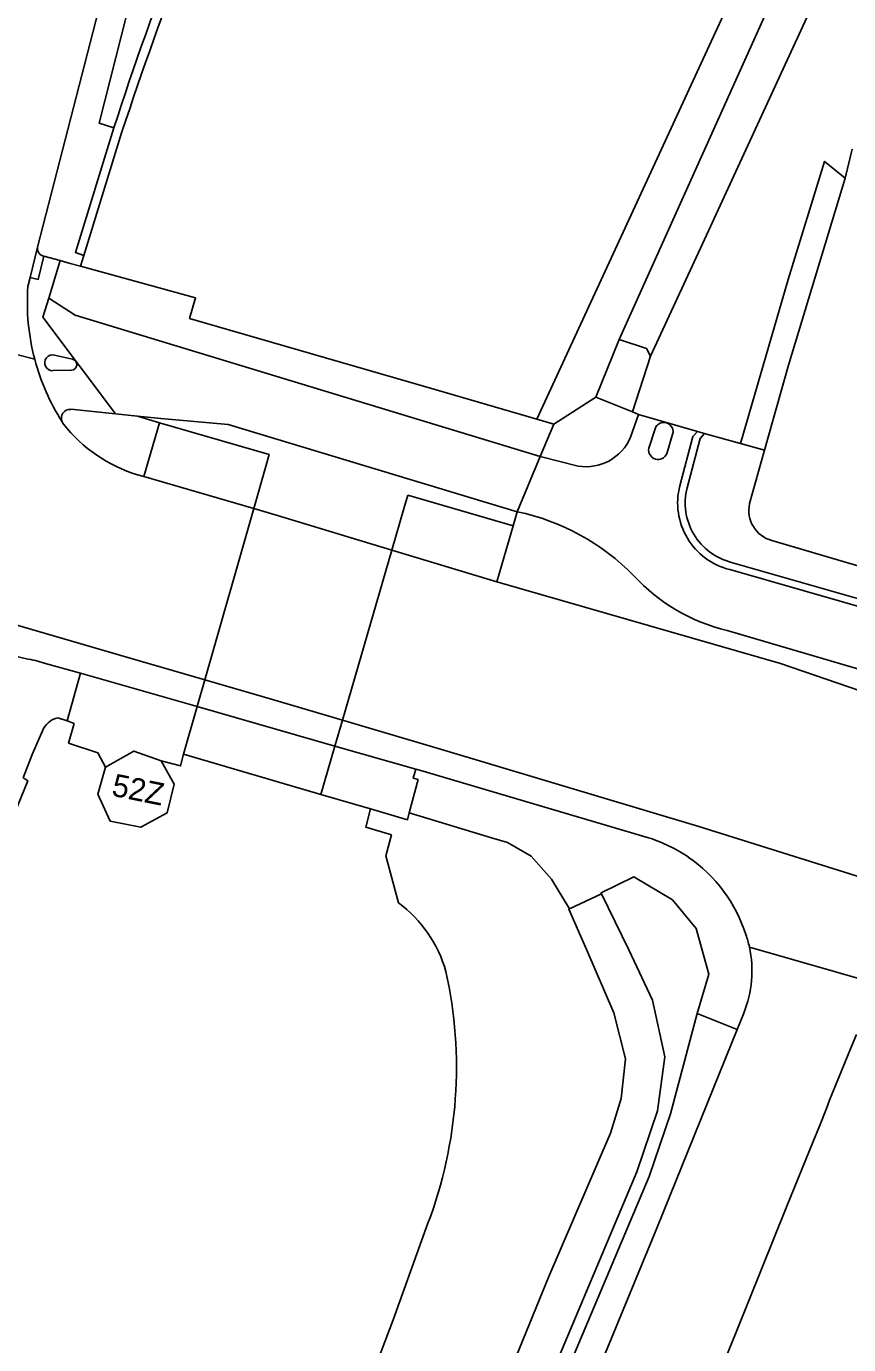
# Model space of a CAD drawing. Extents: x 194485 to 197793, y 468269 to 470822.
# Drawn here: x 194827.4 to 194871.3, y 469975.4 to 470045.7 of the extents above; entities that cross this region are included whole.
import ezdxf

# ---------------------------------------------------------------- set-up
doc = ezdxf.new("R2010")
doc.units = 0
for name, color, linetype in [('BGT grensvlak onbegroeid terreindeel', 7, 'Continuous'), ('BGT grensvlak overbruggingsdeel plus 1', 7, 'Continuous'), ('BGT grensvlak pand op maaiveld', 7, 'Continuous'), ('BGT grensvlak scheiding', 7, 'Continuous'), ('BGT grensvlak vegetatieobject', 7, 'Continuous'), ('BGT grensvlak waterdeel', 7, 'Continuous'), ('BGT grensvlak wegdeel', 7, 'Continuous'), ('BGT grensvlak wegdeel plus 1', 7, 'Continuous'), ('BGT lijnelement scheiding kademuur', 7, 'Continuous'), ('BGT tekst huisnummerreeks', 7, 'Continuous'), ('GEM grensvlak beperking object', 7, 'Continuous')]:
    doc.layers.add(name, color=color, linetype=linetype)

msp = doc.modelspace()

# ---------------------------------------------------------------- linework, layer by layer
at = {"layer": 'BGT grensvlak onbegroeid terreindeel'}
msp.add_line((194840.206, 470022.301), (194839.549, 470019.999), dxfattribs=at)
msp.add_line((194840.206, 470022.301), (194839.549, 470019.999), dxfattribs=at)
msp.add_lwpolyline([(194834.524, 470024.573), (194840.367, 470022.867), (194840.206, 470022.301)], dxfattribs=at)
msp.add_lwpolyline([(194834.524, 470024.573), (194840.367, 470022.867), (194840.206, 470022.301)], dxfattribs=at)
at = {"layer": 'BGT grensvlak overbruggingsdeel plus 1'}
for p, q in [((194828.616, 470031.214), (194829.221, 470033.217)), ((194828.616, 470031.214), (194829.221, 470033.217)), ((194833.352, 470024.915), (194832.171, 470025.038)), ((194833.352, 470024.915), (194832.171, 470025.038)), ((194833.352, 470024.915), (194832.171, 470025.038)), ((194833.352, 470024.915), (194834.524, 470024.573)), ((194833.352, 470024.915), (194834.524, 470024.573)), ((194834.524, 470024.573), (194833.691, 470021.696)), ((194855.556, 470024.502), (194854.65, 470024.764)), ((194855.556, 470024.502), (194854.65, 470024.764)), ((194855.556, 470024.502), (194854.65, 470024.764)), ((194855.556, 470024.502), (194854.833, 470022.772)), ((194855.556, 470024.502), (194854.833, 470022.772)), ((194855.556, 470024.502), (194854.833, 470022.772)), ((194854.833, 470022.772), (194853.6, 470019.823)), ((194854.833, 470022.772), (194853.6, 470019.823)), ((194854.833, 470022.772), (194853.6, 470019.823)), ((194833.691, 470021.696), (194839.549, 470019.999)), ((194836.943, 470010.858), (194839.549, 470019.999)), ((194836.943, 470010.858), (194839.549, 470019.999)), ((194839.549, 470019.999), (194840.821, 470019.631)), ((194839.549, 470019.999), (194840.821, 470019.631)), ((194840.821, 470019.631), (194846.917, 470017.781)), ((194840.821, 470019.631), (194846.917, 470017.781)), ((194853.6, 470019.823), (194853.382, 470019.067)), ((194853.6, 470019.823), (194853.382, 470019.067)), ((194853.6, 470019.823), (194853.382, 470019.067)), ((194853.382, 470019.067), (194852.523, 470016.08)), ((194853.382, 470019.067), (194852.523, 470016.08)), ((194853.382, 470019.067), (194852.523, 470016.08)), ((194844.284, 470008.708), (194846.917, 470017.781)), ((194844.284, 470008.708), (194846.917, 470017.781)), ((194846.917, 470017.781), (194852.523, 470016.08)), ((194846.917, 470017.781), (194852.523, 470016.08)), ((194836.538, 470009.439), (194836.943, 470010.858)), ((194835.81, 470006.886), (194836.538, 470009.439)), ((194843.879, 470007.314), (194844.284, 470008.708)), ((194843.879, 470007.314), (194844.284, 470008.708)), ((194843.136, 470004.745), (194835.81, 470006.886)), ((194843.879, 470007.314), (194843.136, 470004.745)), ((194843.879, 470007.314), (194843.136, 470004.745))]:
    msp.add_line(p, q, dxfattribs=at)
for points in [[(194829.221, 470033.217), (194829.753, 470033.07), (194830.318, 470032.914)], [(194829.221, 470033.217), (194829.753, 470033.07), (194830.318, 470032.914)], [(194854.65, 470024.764), (194849.288, 470026.317), (194836.133, 470030.126), (194836.444, 470031.223), (194830.318, 470032.914)], [(194854.65, 470024.764), (194849.288, 470026.317), (194836.133, 470030.126), (194836.444, 470031.223), (194830.318, 470032.914)], [(194854.65, 470024.764), (194849.288, 470026.317), (194836.133, 470030.126), (194836.444, 470031.223), (194830.318, 470032.914)], [(194832.171, 470025.038), (194828.309, 470030.198), (194828.616, 470031.214)], [(194832.171, 470025.038), (194828.309, 470030.198), (194828.616, 470031.214)], [(194832.171, 470025.038), (194828.309, 470030.198), (194828.616, 470031.214)]]:
    msp.add_lwpolyline(points, dxfattribs=at)
at = {"layer": 'BGT grensvlak pand op maaiveld'}
for points in [[(194831.651, 470006.204), (194833.161, 470007.055), (194834.611, 470006.546)], [(194831.651, 470006.204), (194831.231, 470004.754), (194831.892, 470003.324), (194833.522, 470002.995), (194834.931, 470003.765), (194835.311, 470005.286), (194834.611, 470006.546)]]:
    msp.add_lwpolyline(points, dxfattribs=at)
at = {"layer": 'BGT grensvlak scheiding'}
msp.add_line((194832.525, 470040.079), (194830.496, 470033.492), dxfattribs=at)
msp.add_line((194832.525, 470040.079), (194830.496, 470033.492), dxfattribs=at)
for points in [[(194832.096, 470040.306), (194830.038, 470033.652), (194830.496, 470033.492)], [(194827.255, 470005.625), (194827.289, 470005.613), (194827.504, 470005.47), (194823.464, 469995.624), (194818.884, 469984.242), (194815.386, 469975.571), (194810.889, 469964.477), (194809.044, 469959.222), (194808.956, 469959.251), (194808.754, 469958.624), (194808.82, 469958.595), (194806.407, 469951.632), (194802.367, 469939.901), (194798.628, 469929.158), (194794.367, 469916.818), (194790.421, 469905.459), (194786.654, 469894.582), (194784.195, 469887.31), (194784.137, 469887.337), (194783.919, 469886.705), (194783.996, 469886.659), (194782.911, 469883.392), (194782.568, 469882.34)]]:
    msp.add_lwpolyline(points, dxfattribs=at)
for centre, radius, start, end in [((195009.78, 469982.726), 186.781, 155.64819, 162.04468), ((195025.409, 469976.503), 203.092, 155.86222, 161.75749), ((195025.409, 469976.503), 203.092, 155.86222, 161.75749)]:
    msp.add_arc(centre, radius, start, end, dxfattribs=at)
at = {"layer": 'BGT grensvlak vegetatieobject'}
msp.add_lwpolyline([(194863.209, 469993.056), (194861.772, 469987.709), (194860.635, 469984.363), (194856.079, 469973.541), (194855.432, 469973.807)], dxfattribs=at)
at = {"layer": 'BGT grensvlak waterdeel'}
for points in [[(194854.65, 470024.764), (194867.175, 470051.893), (194870.503, 470058.597), (194876.69, 470072.295), (194880.588, 470080.32), (194883.876, 470087.874), (194887.774, 470096.339), (194894.6, 470110.507), (194899.128, 470120.323), (194907.754, 470136.943), (194911.472, 470144.338), (194914.93, 470150.862), (194921.547, 470163.7), (194928.804, 470177.288), (194936.4, 470191.987), (194953.848, 470226.803)], [(194847.279, 469998.96), (194846.6, 470001.465), (194846.897, 470002.596), (194845.525, 470003.003), (194845.777, 470003.973)], [(194847.279, 469998.96), (194846.6, 470001.465), (194846.897, 470002.596), (194845.525, 470003.003), (194845.777, 470003.973)], [(194836.283, 469948.995), (194841.759, 469962.936), (194846.996, 469976.731), (194848.845, 469981.874)], [(194836.283, 469948.995), (194841.759, 469962.936), (194846.996, 469976.731), (194848.845, 469981.874)]]:
    msp.add_lwpolyline(points, dxfattribs=at)
for centre, radius, start, end in [((194843.162, 469993.416), 6.905, 15.849, 53.40437), ((194843.162, 469993.416), 6.905, 15.849, 53.40437), ((194826.748, 469990.202), 23.615, 339.34941, 12.47208), ((194826.748, 469990.202), 23.615, 339.34941, 12.47208)]:
    msp.add_arc(centre, radius, start, end, dxfattribs=at)
at = {"layer": 'BGT grensvlak wegdeel'}
for p, q in [((194859.038, 470029.001), (194879.003, 470073.442)), ((194871.47, 470039.158), (194871.091, 470037.608)), ((194868.077, 470027.632), (194871.091, 470037.608)), ((194827.633, 470032.317), (194828.02, 470033.933)), ((194828.365, 470033.453), (194829.221, 470033.217)), ((194830.496, 470033.492), (194830.318, 470032.914)), ((194830.496, 470033.492), (194830.318, 470032.914)), ((194827.509, 470031.83), (194827.633, 470032.317)), ((194865.506, 470023.461), (194868.055, 470032.212)), ((194827.87, 470027.952), (194822.001, 470029.453)), ((194859.038, 470029.001), (194857.793, 470025.932)), ((194829.894, 470027.96), (194828.922, 470028.176)), ((194860.718, 470028.118), (194859.748, 470025.143)), ((194828.834, 470027.347), (194829.836, 470027.37)), ((194866.801, 470023.102), (194868.077, 470027.632)), ((194857.793, 470025.932), (194855.556, 470024.502)), ((194857.793, 470025.932), (194859.748, 470025.143)), ((194832.171, 470025.038), (194829.79, 470025.285)), ((194859.65, 470023.798), (194860.08, 470025.009)), ((194859.748, 470025.143), (194860.08, 470025.009)), ((194863.22, 470024.103), (194860.08, 470025.009)), ((194860.977, 470024.304), (194860.617, 470023.208)), ((194861.586, 470022.916), (194861.913, 470024.02)), ((194863.597, 470023.993), (194863.22, 470024.103)), ((194863.766, 470023.943), (194863.597, 470023.993)), ((194863.766, 470023.943), (194865.506, 470023.461)), ((194865.506, 470023.461), (194866.801, 470023.102)), ((194866.801, 470023.102), (194866, 470020.256)), ((194854.833, 470022.772), (194856.855, 470022.257)), ((194833.361, 470021.792), (194833.691, 470021.696)), ((194847.765, 470020.707), (194853.382, 470019.067)), ((194847.765, 470020.707), (194853.382, 470019.067)), ((194847.765, 470020.707), (194853.382, 470019.067)), ((194847.765, 470020.707), (194853.382, 470019.067)), ((194864.942, 470016.736), (194921.034, 470000.657)), ((194865.039, 470017.124), (194921.144, 470001.042)), ((194864.799, 470013.487), (194872.735, 470011.158)), ((194830.308, 470011.206), (194828.383, 470011.748)), ((194829.596, 470008.665), (194830.308, 470011.206)), ((194836.538, 470009.439), (194830.308, 470011.206)), ((194829.101, 470008.835), (194829.596, 470008.665)), ((194829.596, 470008.665), (194829.979, 470008.534)), ((194843.879, 470007.314), (194848.197, 470006.102)), ((194848.326, 470005.542), (194847.843, 470003.759)), ((194845.777, 470003.973), (194843.136, 470004.745)), ((194845.777, 470003.973), (194843.136, 470004.745)), ((194881.775, 469997.26), (194863.283, 470003.031)), ((194856.393, 469998.649), (194858.105, 469999.447)), ((194874.488, 469994.15), (194865.987, 469996.608)), ((194865.335, 469992.211), (194863.209, 469993.056)), ((194865.686, 469993.077), (194865.335, 469992.211))]:
    msp.add_line(p, q, dxfattribs=at)
for points in [[(194881.841, 470073.941), (194874.956, 470058.997), (194866.739, 470041.161), (194863.489, 470034.107), (194860.718, 470028.118)], [(194828.02, 470033.933), (194832.743, 470052.301), (194834.678, 470060.291)], [(194835.157, 470055.761), (194831.309, 470040.542), (194832.096, 470040.306)], [(194868.055, 470032.212), (194870.001, 470038.508), (194871.091, 470037.608)], [(194828.365, 470033.453), (194828.058, 470032.209), (194827.633, 470032.317)], [(194859.038, 470029.001), (194860.495, 470028.522), (194860.718, 470028.118)], [(194862.274, 470021.202), (194862.97, 470023.827), (194863.22, 470024.103)], [(194862.662, 470021.104), (194863.358, 470023.729), (194863.597, 470023.993)], [(194846.917, 470017.781), (194847.576, 470020.054), (194847.765, 470020.707)], [(194846.917, 470017.781), (194847.576, 470020.054), (194847.765, 470020.707)], [(194846.917, 470017.781), (194847.576, 470020.054), (194847.765, 470020.707)], [(194846.917, 470017.781), (194847.576, 470020.054), (194847.765, 470020.707)], [(194867.191, 470018.283), (194888.632, 470011.972), (194893.555, 470010.494), (194928.526, 470000.437), (194932.598, 469998.942), (194932.537, 469998.647), (194933.903, 469998.362), (194934.354, 469998.688), (194957.269, 469992.088), (194960.119, 469991.507), (194973.489, 469987.631), (194979.369, 469987.518), (194988.676, 469984.802)], [(194818.614, 470016.183), (194832.407, 470012.175), (194836.943, 470010.858)], [(194818.614, 470016.183), (194832.407, 470012.175), (194836.943, 470010.858)], [(194852.523, 470016.08), (194867.652, 470011.725), (194872.515, 470010.054)], [(194852.523, 470016.08), (194867.652, 470011.725), (194872.515, 470010.054)], [(194819.527, 470013.746), (194825.536, 470012.429), (194827.425, 470011.977)], [(194828.353, 470008.293), (194827.734, 470006.883), (194827.255, 470005.625)], [(194831.651, 470006.204), (194831.241, 470006.964), (194829.681, 470007.474), (194829.979, 470008.534)], [(194844.284, 470008.708), (194849.517, 470007.162), (194863.283, 470003.031)], [(194834.611, 470006.546), (194835.651, 470006.266), (194835.81, 470006.886)], [(194848.197, 470006.102), (194848.055, 470005.622), (194848.326, 470005.542)], [(194860.602, 470002.434), (194848.455, 470006.026), (194848.197, 470006.102)], [(194845.777, 470003.973), (194847.745, 470003.397), (194847.843, 470003.759)], [(194856.393, 469998.649), (194855.438, 470000.223), (194854.357, 470001.461), (194853.078, 470002.184), (194852.238, 470002.433), (194847.843, 470003.759)], [(194863.209, 469993.056), (194863.826, 469995.162), (194863.145, 469997.59), (194861.883, 469999.117), (194859.831, 470000.35), (194858.078, 469999.501), (194858.105, 469999.447)], [(194858.105, 469999.447), (194859.551, 469996.461), (194860.816, 469993.781), (194861.483, 469990.746), (194861.088, 469987.871), (194859.98, 469984.612), (194855.432, 469973.807)], [(194856.393, 469998.649), (194856.354, 469998.631), (194857.318, 469996.44), (194858.752, 469993.092), (194859.38, 469990.646), (194859.152, 469988.524), (194858.575, 469986.676), (194855.284, 469979.032), (194853.032, 469973.502)], [(194865.335, 469992.211), (194864.053, 469989.052), (194861.058, 469981.614), (194858.758, 469976.055), (194857.627, 469973.291), (194857.254, 469972.351), (194855.364, 469967.699), (194854.984, 469966.762), (194852.721, 469961.204), (194850.829, 469956.564), (194849.79, 469953.734), (194849.233, 469951.806), (194848.882, 469950.363), (194848.438, 469948.489), (194846.978, 469941.616), (194844.497, 469929.852), (194842.83, 469922.008), (194841.242, 469914.511), (194841.051, 469913.561), (194841.05, 469913.555)], [(194854.058, 469946.01), (194854.601, 469948.505), (194855.17, 469950.829), (194855.821, 469952.8), (194856.186, 469953.729), (194859.198, 469961.162), (194859.585, 469962.105), (194862.649, 469969.624), (194865.28, 469976.077), (194867.985, 469982.792), (194869.392, 469986.244), (194869.721, 469987.063), (194870.093, 469987.991), (194870.263, 469988.438), (194871.388, 469991.183), (194871.697, 469991.947)]]:
    msp.add_lwpolyline(points, dxfattribs=at)
for centre, radius, start, end in [((194828.44, 470033.871), 0.424, 171.5783, 259.83508), ((194839.256, 470030.968), 11.778, 175.8015, 194.83509), ((194839.272, 470030.968), 11.794, 194.81572, 212.60851), ((194828.822, 470027.767), 0.421, 76.27592, 271.60534), ((194829.81, 470027.67), 0.302, 274.96763, 73.80352), ((194829.767, 470024.811), 0.474, 87.231, 204.87957), ((194829.763, 470024.809), 0.469, 204.86886, 221.06995), ((194835.674, 470029.403), 7.955, 218.04246, 253.09816), ((194861.423, 470024.09), 0.495, 351.92587, 154.31656), ((194857.272, 470024.806), 2.582, 260.70338, 337.03617), ((194861.12, 470023.123), 0.51, 170.45581, 336.00471), ((194865.834, 470020.299), 3.673, 165.75995, 255.94846), ((194865.833, 470020.298), 3.272, 165.7446, 255.94975), ((194867.628, 470019.893), 1.668, 167.43511, 254.79939), ((194851.08, 470007.829), 12.256, 44.44715, 78.13623), ((194867.116, 470023.108), 9.896, 222.58899, 256.46178), ((194826.522, 470006.079), 5.967, 71.82155, 81.29106), ((194829.354, 470007.699), 1.164, 102.5439, 149.3102), ((194858.205, 469994.789), 8.012, 55.60117, 72.58955), ((194858.227, 469994.844), 7.953, 17.75612, 55.51165), ((194860.028, 469995.3), 6.101, 12.38408, 18.84262), ((194860.145, 469995.328), 5.98, 337.89256, 12.36264)]:
    msp.add_arc(centre, radius, start, end, dxfattribs=at)
at = {"layer": 'BGT grensvlak wegdeel plus 1'}
for p, q in [((194828.616, 470031.214), (194830.031, 470030.304)), ((194828.616, 470031.214), (194830.031, 470030.304)), ((194838.19, 470024.473), (194853.6, 470019.823)), ((194838.19, 470024.473), (194853.6, 470019.823)), ((194836.538, 470009.439), (194843.879, 470007.314))]:
    msp.add_line(p, q, dxfattribs=at)
for points in [[(194830.031, 470030.304), (194848.8, 470024.604), (194854.833, 470022.772)], [(194830.031, 470030.304), (194848.8, 470024.604), (194854.833, 470022.772)], [(194838.19, 470024.473), (194834.591, 470024.802), (194833.352, 470024.915)], [(194838.19, 470024.473), (194834.591, 470024.802), (194833.352, 470024.915)], [(194836.943, 470010.858), (194840.547, 470009.812), (194844.284, 470008.708)]]:
    msp.add_lwpolyline(points, dxfattribs=at)
at = {"layer": 'BGT lijnelement scheiding kademuur'}
msp.add_line((194830.496, 470033.492), (194830.318, 470032.914), dxfattribs=at)
at = {"layer": 'GEM grensvlak beperking object'}
msp.add_lwpolyline([(194831.231, 470004.754), (194831.892, 470003.324), (194833.522, 470002.995), (194834.931, 470003.765), (194835.311, 470005.286), (194834.611, 470006.546), (194833.161, 470007.055), (194831.651, 470006.204), (194831.231, 470004.754)], dxfattribs=at)

# ---------------------------------------------------------------- texts
at = {"layer": 'BGT tekst huisnummerreeks'}
msp.add_text('52Z', height=1.2, rotation=348.6, dxfattribs=at).set_placement((194831.922, 470004.69))

doc.saveas('drawing.dxf')
